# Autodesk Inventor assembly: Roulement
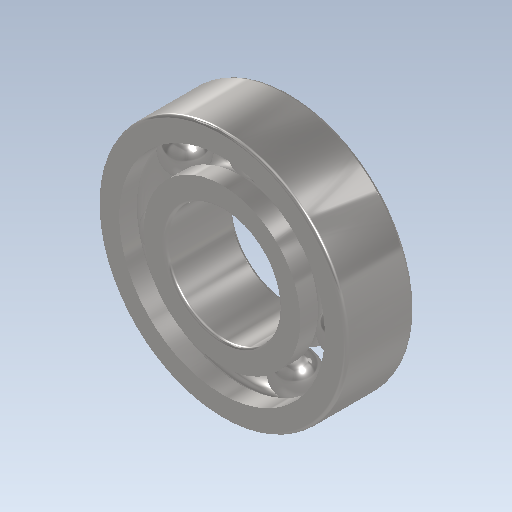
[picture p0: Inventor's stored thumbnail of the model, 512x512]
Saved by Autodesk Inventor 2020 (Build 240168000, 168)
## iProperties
ClientObjectVersion: 1
Created: 2023-10
Part Number: Roulement
Document SubType Name: Assembly
Designer: bruno
Author: bruno
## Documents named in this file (2)
- C:\Users\bruno\Documents\1-Cours-2023-24\Maquettes-Inventor\Pince-robot-Dobot\HS422\Servo\Design Accelerator\Roulement1.iam
- C:\Users\bruno\Documents\Inventor\Content Center Files\R2020\fr-FR\SKF - Single row ball bearings\SKF618_5.ipt
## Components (1 placed, 1 different names)
1. SKF- roulements à une rangée de billes SKF618/5:1
